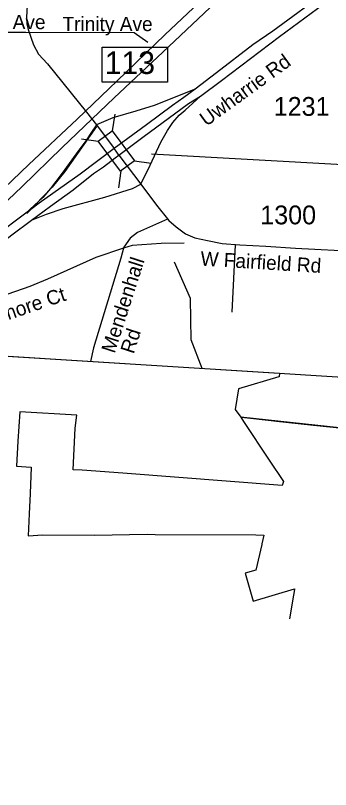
# Model space of a CAD drawing. Extents: x 1662474 to 1856135, y 779280 to 917889.
# Drawn here: x 1699151 to 1701248, y 788215 to 793367 of the extents above; entities that cross this region are included whole.
import ezdxf

# ---------------------------------------------------------------- set-up
doc = ezdxf.new("R2010")
doc.units = 0
for name, color, linetype in [('Exist Boundary Political City Limit New', 7, 'Continuous'), ('Exist Boundary Political CountyLine', 7, 'Continuous'), ('Exist Hydrographic Misc Water Feature', 7, 'Continuous'), ('Exist Road Non-System Type 51', 7, 'Continuous'), ('Exist Road Non-System Type 51 Label', 7, 'Continuous'), ('Exist Road Primary Interstate Divided Center Attributed', 7, 'Continuous'), ('Exist Road Primary Interstate Interchange CELL', 7, 'Continuous'), ('Exist Road Primary Interstate Ramp 1 Lane Attributed', 7, 'Continuous'), ('Exist Road Secondary Structure Standard Bridge CELL', 7, 'Continuous'), ('Exist Road Secondary Structure Standard Bridge Number Label', 7, 'Continuous'), ('Exist Road Secondary Type 51 Attributed', 7, 'Continuous'), ('Exist Road Secondary Type 51 Label', 7, 'Continuous'), ('Exist Road Secondary Type 51 Number Label', 7, 'Continuous'), ('Exist Utilities Electrical Transmission Line', 7, 'Continuous'), ('Map Preparation Boundary City Limit Buffer Line', 7, 'Continuous')]:
    doc.layers.add(name, color=color, linetype=linetype)

msp = doc.modelspace()

# ---------------------------------------------------------------- linework, layer by layer
at = {"layer": 'Exist Boundary Political City Limit New'}
for points in [[(1697460, 791201.2), (1700908.6, 790986.9), (1700905.6, 790961.5), (1700903.5, 790961.6), (1700635.9, 790882.4), (1700612.5, 790743.9), (1700651, 790693.2)], [(1700651, 790693.2), (1700654.2, 790692.9), (1700851.9, 790671.3), (1700889, 790667.2), (1701135.4, 790640.3), (1701307.2, 790621.5), (1701357.1, 790621.1), (1701364.8, 790709), (1701386.2, 790956.2)], [(1700651, 790693.2), (1700667.5, 790664.8), (1700839, 790408.1), (1700933.9, 790266.2), (1700924.8, 790237.8), (1699865.9, 790321.2), (1699594.6, 790341.2), (1699534.5, 790342.4), (1699548.9, 790619.4), (1699559.1, 790706.2), (1699179, 790729.8), (1699167.1, 790533), (1699157, 790366.8), (1699255.8, 790361.4), (1699247.9, 790184.5), (1699242, 790050.2), (1699235.4, 789903.4), (1699334, 789909.8), (1699677.1, 789908.6), (1700027, 789914.1), (1700080, 789913.3)], [(1701307.2, 790621.5), (1700651, 790693.2)], [(1700080, 789913.3), (1700749.8, 789909), (1700804.6, 789908.6), (1700790.9, 789850.1), (1700790, 789846.1), (1700750.2, 789675.8), (1700678.6, 789654.9), (1700733, 789468.4)], [(1700733, 789468.4), (1701008.9, 789550.2), (1701008.1, 789546.7)], [(1701008.1, 789546.7), (1701000.6, 789508.2), (1700973.5, 789351.9)]]:
    msp.add_lwpolyline(points, dxfattribs=at)
at = {"layer": 'Exist Boundary Political CountyLine'}
msp.add_lwpolyline([(1690037.5, 791664.5), (1701364.2, 790957.5), (1714716, 790252.3), (1740499.2, 788706.5), (1750629.1, 788065.3), (1759370.2, 787540.1), (1762189.4, 787333), (1768414.3, 786933.6), (1776472.8, 786425.7), (1794607.1, 785397.2), (1814974.6, 784258.7), (1839558.3, 782880.6)], dxfattribs=at)
at = {"layer": 'Exist Hydrographic Misc Water Feature'}
msp.add_lwpolyline([(1700393.7, 791017.7), (1700320.9, 791207.9), (1700314.9, 791483.8), (1700209.9, 791725.5)], dxfattribs=at)
at = {"layer": 'Exist Road Non-System Type 51'}
msp.add_line((1700612.6, 791841.4), (1700590.8, 791393.2), dxfattribs=at)
for points in [[(1699219.6, 793254.2), (1699037.8, 793254.9), (1698582.4, 793273.1)], [(1700031.8, 793188.5), (1699941.4, 793251.8), (1699219.6, 793254.2)], [(1699691.1, 792629), (1699479.8, 792329), (1699394.5, 792224), (1699227.2, 792048.9)], [(1700162.9, 792011.9), (1699962.1, 791922.4), (1699914.9, 791885.2), (1699872.6, 791826.1), (1699870.6, 791817.9)], [(1700272.9, 791852.1), (1700120.1, 791850.5), (1699926.5, 791835.9), (1699870.6, 791817.9)], [(1699870.6, 791817.9), (1699685.9, 791757.1), (1699364, 791612.7), (1699246.4, 791563.7), (1698797.4, 791408.2), (1698727.9, 791393), (1698640.9, 791390.7)], [(1699870.6, 791817.9), (1699852.5, 791750.8), (1699669.8, 791154.8), (1699650.2, 791064.5)]]:
    msp.add_lwpolyline(points, dxfattribs=at)
at = {"layer": 'Exist Road Primary Interstate Divided Center Attributed'}
for points in [[(1700381.7, 792830.1), (1700522.6, 792935.7), (1700907.4, 793226.8), (1701330.4, 793540.5), (1701557.2, 793709.6), (1701883.2, 793948.4), (1702037, 794061.4), (1702197.8, 794175), (1702495.5, 794366.2), (1702639.7, 794446.7), (1702844.8, 794557.1), (1703184.9, 794739)], [(1702853.3, 794630.4), (1702750.9, 794569.7), (1702479, 794418), (1702226.1, 794261.6), (1702015.2, 794111.1), (1701830, 793976.6), (1701479.5, 793719.9), (1701237.6, 793540), (1700863.6, 793263), (1700730.9, 793171.6), (1700489.1, 792985.6), (1700346.4, 792876.8)], [(1700346.4, 792876.8), (1700271.1, 792821.7), (1700195.9, 792767.5), (1700023.5, 792639.4), (1699807.1, 792483)], [(1699839.4, 792438.1), (1699997.8, 792556.3), (1700301.3, 792782), (1700381.7, 792830.1)], [(1699807.1, 792483), (1699580.7, 792310.6), (1699308.8, 792117.5), (1699260.9, 792081.8), (1699219.1, 792051.2)], [(1699257.1, 792004.9), (1699383.9, 792098.1), (1699534.1, 792207), (1699670.2, 792314.5), (1699737.4, 792360.2), (1699815.2, 792419.3), (1699839.4, 792438.1)], [(1699219.1, 792051.2), (1699010.4, 791896.5), (1698691.7, 791656), (1698432.9, 791473.5), (1698320.2, 791401), (1698179.9, 791324.7), (1697969.6, 791230.9), (1697860.8, 791176.2)], [(1697980.4, 791168.7), (1698186.5, 791266.8), (1698330.4, 791342.6), (1698444.4, 791410), (1698554.4, 791485.8), (1698763, 791637), (1698872.7, 791723.4), (1699013.4, 791821.6), (1699127.4, 791907.4), (1699257.1, 792004.9)]]:
    msp.add_lwpolyline(points, dxfattribs=at)
at = {"layer": 'Exist Road Primary Interstate Interchange CELL'}
msp.add_lwpolyline([(1699727.1, 793156.2), (1700162, 793156.2), (1700162, 792923), (1699727.1, 792923)], close=True, dxfattribs=at)
at = {"layer": 'Exist Road Primary Interstate Ramp 1 Lane Attributed'}
for points in [[(1700346.4, 792876.8), (1700073, 792768.6), (1699952.2, 792731), (1699799.1, 792685.3), (1699689, 792639.6)], [(1699984.4, 792244.7), (1700046.2, 792370.9), (1700118.7, 792524.1), (1700161.6, 792602), (1700199.2, 792655.7), (1700239.5, 792704.1), (1700279.8, 792736.3), (1700381.7, 792830.1)], [(1699689, 792639.6), (1699656.8, 792591.2), (1699619.2, 792532.1), (1699554.8, 792446.2), (1699460.8, 792317.2), (1699382.9, 792215.1), (1699331.9, 792156), (1699219.1, 792051.2)], [(1699257.1, 792004.9), (1699357, 792044.4), (1699467.2, 792082.1), (1699745.4, 792158.7), (1699930.7, 792215.1), (1699984.4, 792244.7)]]:
    msp.add_lwpolyline(points, dxfattribs=at)
at = {"layer": 'Exist Road Secondary Structure Standard Bridge CELL'}
for p, q in [((1699811.4, 792711.5), (1699795.1, 792599.5)), ((1699590.3, 792546.5), (1699702.3, 792530.3)), ((1699942.9, 792400.5), (1700054.9, 792384.3)), ((1699852.2, 792332.9), (1699836, 792220.8))]:
    msp.add_line(p, q, dxfattribs=at)
msp.add_lwpolyline([(1699795.1, 792599.5), (1699943.4, 792400.9), (1699850.6, 792331.6), (1699702.3, 792530.3)], close=True, dxfattribs=at)
at = {"layer": 'Exist Road Secondary Structure Standard Bridge Number Label'}
msp.add_line((1700055.8, 792446.3), (1702450.8, 792314), dxfattribs=at)
at = {"layer": 'Exist Road Secondary Type 51 Attributed'}
for points in [[(1699351.2, 795502.4), (1699340.2, 795308.1), (1699335.2, 795150.8), (1699320.6, 794867.8), (1699279.8, 794298.9), (1699262.2, 793940.1), (1699238.9, 793630.9), (1699224.3, 793356.7), (1699227.2, 793310), (1699236, 793275), (1699270.1, 793171.6), (1699305.1, 793109.8), (1699364.1, 793045.3), (1699624.6, 792722.9), (1699689, 792639.6)], [(1699689, 792639.6), (1699807.1, 792483)], [(1699839.4, 792438.1), (1699820.6, 792465), (1699807.1, 792483)], [(1699839.4, 792438.1), (1699984.4, 792244.7)], [(1699984.4, 792244.7), (1700089.1, 792105), (1700172.4, 792002.9), (1700220.7, 791959.9), (1700282.5, 791914.2), (1700344.2, 791887.3), (1700428.4, 791869.5), (1700526.3, 791850.4), (1700644.4, 791841.4), (1700817.1, 791832.4), (1701014.5, 791819), (1701441.7, 791795.9)]]:
    msp.add_lwpolyline(points, dxfattribs=at)
at = {"layer": 'Exist Utilities Electrical Transmission Line'}
for points in [[(1704176.7, 796741.9), (1703861.4, 796548), (1703690.7, 796431), (1703099.6, 795902.8), (1701742.3, 794638.8), (1701249.7, 794222.9), (1701018.9, 794076.3), (1700799.5, 793859.5), (1700485.9, 793563.3), (1700145.8, 793239.3), (1699828.1, 792932.9), (1699560.7, 792676.4), (1699238.8, 792376.4), (1698967.3, 792115.7), (1698848.5, 792002.6), (1698780.1, 791948.8), (1698452.8, 791705), (1698238, 791554.1), (1697906.8, 791173.4)], [(1704303, 796746.1), (1703891.2, 796491.9), (1703732.7, 796382.9), (1703603.9, 796265.3), (1703350.3, 796026.9), (1703004.5, 795712.9), (1702646.5, 795380.8), (1702288.8, 795045.1), (1701898.4, 794681.1), (1701550.5, 794361.3), (1701329.2, 794162.6), (1701070.3, 794003.7), (1700847.2, 793799.2), (1700523.3, 793495.2), (1700131.3, 793123.4), (1699807.4, 792819.1), (1699461.3, 792489.1), (1699192.1, 792226.7), (1698964.9, 792011.7), (1698837.9, 791900.7), (1698506.5, 791650.4), (1698309.9, 791503.8), (1698006.2, 791167.8)]]:
    msp.add_lwpolyline(points, dxfattribs=at)
at = {"layer": 'Map Preparation Boundary City Limit Buffer Line'}
for points in [[(1697460, 791201.2), (1700908.6, 790986.9), (1700905.6, 790961.5), (1700903.5, 790961.6), (1700635.9, 790882.4), (1700612.5, 790743.9), (1700651, 790693.2)], [(1700651, 790693.2), (1700654.2, 790692.9), (1700851.9, 790671.3), (1700889, 790667.2), (1701135.4, 790640.3), (1701307.2, 790621.5), (1701357.1, 790621.1), (1701364.8, 790709), (1701386.2, 790956.2)], [(1700651, 790693.2), (1700667.5, 790664.8), (1700839, 790408.1), (1700933.9, 790266.2), (1700924.8, 790237.8), (1699865.9, 790321.2), (1699594.6, 790341.2), (1699534.5, 790342.4), (1699548.9, 790619.4), (1699559.1, 790706.2), (1699179, 790729.8), (1699167.1, 790533), (1699157, 790366.8), (1699255.8, 790361.4), (1699247.9, 790184.5), (1699242, 790050.2), (1699235.4, 789903.4), (1699334, 789909.8), (1699677.1, 789908.6), (1700027, 789914.1), (1700080, 789913.3)], [(1701307.2, 790621.5), (1700651, 790693.2)], [(1700080, 789913.3), (1700749.8, 789909), (1700804.6, 789908.6), (1700790.9, 789850.1), (1700790, 789846.1), (1700750.2, 789675.8), (1700678.6, 789654.9), (1700733, 789468.4)], [(1700733, 789468.4), (1701008.9, 789550.2), (1701008.1, 789546.7)], [(1701008.1, 789546.7), (1701000.6, 789508.2), (1700973.5, 789351.9)]]:
    msp.add_lwpolyline(points, dxfattribs=at)

# ---------------------------------------------------------------- texts
at = {"layer": 'Exist Road Non-System Type 51 Label'}
for s, rotation, p in [('Trinity Ave', 359.9919, (1698751, 793276.5)), ('Mendenhall', 72.1443, (1699810.4, 791113.6)), ('Dunmore Ct', 18.8335, (1698846.1, 791251.3)), (' Rd', 72.1443, (1699926.5, 791076.2))]:
    msp.add_text(s, height=95, rotation=rotation, dxfattribs=at).set_placement(p)
msp.add_text('Trinity Ave', height=95, dxfattribs=at).set_placement((1699463.8, 793263.4))
at = {"layer": 'Exist Road Primary Interstate Interchange CELL'}
msp.add_text('113', height=150, dxfattribs=at).set_placement((1699744.6, 792977.9))
at = {"layer": 'Exist Road Secondary Type 51 Label'}
for s, rotation, p in [('Uwharrie Rd', 35.9654, (1700421, 792625.9)), ('W Fairfield Rd', 356.475, (1700379.8, 791702.9))]:
    msp.add_text(s, height=95, rotation=rotation, dxfattribs=at).set_placement(p)
at = {"layer": 'Exist Road Secondary Type 51 Number Label'}
for s, p in [('1231', (1700869.4, 792699.6)), ('1300', (1700779.8, 791977.2))]:
    msp.add_text(s, height=125, dxfattribs=at).set_placement(p)

doc.saveas('drawing.dxf')
